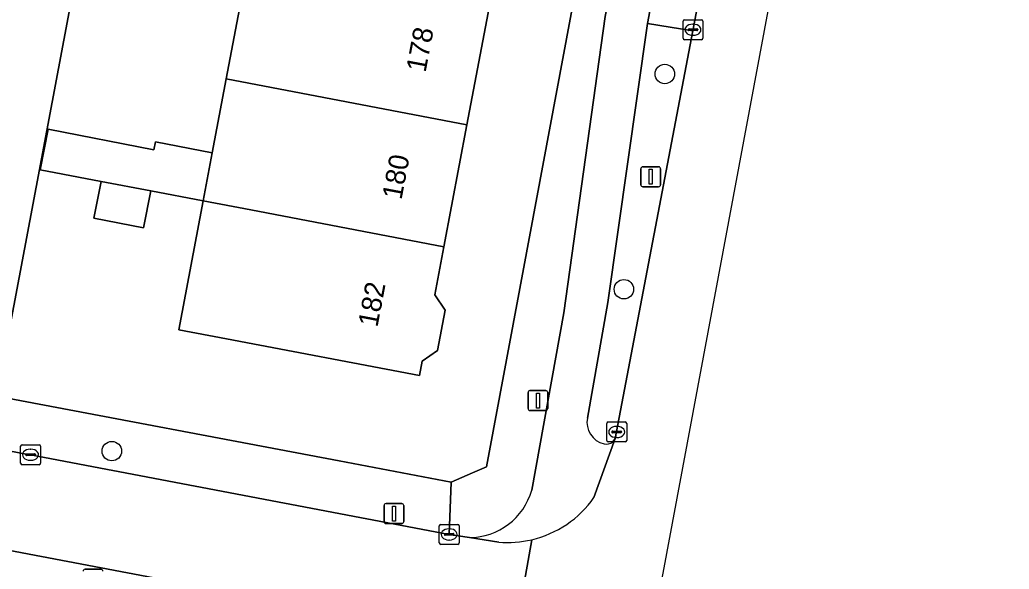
# Model space of a CAD drawing. Extents: x 161258 to 161838, y 380833 to 381727.
# Drawn here: x 161786.15 to 161835.77, y 381531.46 to 381559.03 of the extents above; entities that cross this region are included whole.
import ezdxf

# ---------------------------------------------------------------- set-up
doc = ezdxf.new("R2010")
doc.units = 0
for name, color, linetype in [('IMGEO_Berm_groen', 7, 'Continuous'), ('IMGEO_Boom', 7, 'Continuous'), ('IMGEO_Erf', 7, 'Continuous'), ('IMGEO_Fietspad_open', 7, 'Continuous'), ('IMGEO_Kolk', 7, 'Continuous'), ('IMGEO_Lichtmast', 7, 'Continuous'), ('IMGEO_Pand', 7, 'Continuous'), ('IMGEO_Pand_nummerreeks', 7, 'Continuous'), ('IMGEO_Rijbaan_lokaal_open', 7, 'Continuous'), ('IMGEO_Rijbaan_regionaal_gesloten', 7, 'Continuous'), ('IMGEO_Voetpad_open', 7, 'Continuous')]:
    doc.layers.add(name, color=color, linetype=linetype)

msp = doc.modelspace()

# ---------------------------------------------------------------- linework, layer by layer
at = {"layer": 'IMGEO_Berm_groen'}
for points in [[(161819.903, 381558.473), (161817.626, 381558.84), (161815.643, 381544.847), (161814.615, 381539.044)], [(161815.886, 381537.855), (161816.006, 381538.014), (161819.903, 381558.473)]]:
    msp.add_lwpolyline(points, dxfattribs=at)
for centre, radius, start, end in [((161815.714, 381538.835), 1.119, 169.2571, 256.3919), ((161815.564, 381538.227), 0.492, 256.7259, 310.9123)]:
    msp.add_arc(centre, radius, start, end, dxfattribs=at)
at = {"layer": 'IMGEO_Boom'}
for centre in [(161818.499, 381556.312), (161816.448, 381545.51), (161790.767, 381537.386)]:
    msp.add_circle(centre, 0.489, dxfattribs=at)
at = {"layer": 'IMGEO_Erf'}
for points in [[(161782.505, 381585.389), (161793.109, 381583.267), (161784.977, 381540.142), (161802.164, 381536.901), (161807.78, 381535.827), (161808.863, 381536.294), (161809.558, 381536.593), (161821.924, 381602.839), (161823.603, 381614.49)], [(161809.769, 381560.098), (161808.573, 381553.757), (161807.419, 381547.642), (161806.962, 381545.222), (161807.485, 381544.454), (161807.101, 381542.427), (161806.337, 381541.907), (161806.199, 381541.178), (161796.514, 381543.015), (161794.121, 381543.469), (161795.349, 381549.947), (161792.722, 381550.449), (161792.358, 381548.589), (161789.872, 381549.075), (161790.234, 381550.924), (161787.181, 381551.507), (161787.581, 381553.546), (161792.877, 381552.511), (161792.954, 381552.9), (161795.806, 381552.356), (161796.509, 381556.062), (161797.712, 381562.402)]]:
    msp.add_lwpolyline(points, dxfattribs=at)
at = {"layer": 'IMGEO_Fietspad_open'}
for points in [[(161823.462, 381598.367), (161821.175, 381588.661), (161815.514, 381559.201), (161813.439, 381544.332), (161811.823, 381535.427)], [(161814.615, 381539.044), (161815.643, 381544.847), (161817.626, 381558.84), (161820.504, 381574.1), (161820.891, 381576.15), (161822.952, 381586.933)], [(161814.947, 381535.053), (161816.006, 381538.014), (161815.886, 381537.855)], [(161808.698, 381533.046), (161810.171, 381532.818)]]:
    msp.add_lwpolyline(points, dxfattribs=at)
for centre, radius, start, end in [((161815.714, 381538.835), 1.119, 169.2571, 256.3919), ((161815.564, 381538.227), 0.492, 256.7259, 310.9123), ((161808.685, 381536.305), 3.259, 270.2359, 344.3731), ((161810.611, 381538.095), 5.297, 283.2263, 324.9458), ((161810.612, 381538.134), 5.334, 265.2563, 283.1219)]:
    msp.add_arc(centre, radius, start, end, dxfattribs=at)
at = {"layer": 'IMGEO_Kolk'}
for p, q in [((161819.488, 381559.032), (161820.34, 381559.032)), ((161819.413, 381558.106), (161819.413, 381558.958)), ((161819.672, 381558.526), (161819.672, 381558.538)), ((161819.715, 381558.575), (161820.113, 381558.575)), ((161819.901, 381558.812), (161819.926, 381558.812)), ((161820.156, 381558.538), (161820.156, 381558.526)), ((161820.414, 381558.958), (161820.414, 381558.106)), ((161820.34, 381558.032), (161819.488, 381558.032)), ((161820.11, 381558.489), (161819.712, 381558.489)), ((161819.924, 381558.252), (161819.899, 381558.252)), ((161815.587, 381537.921), (161815.587, 381538.773)), ((161815.662, 381538.847), (161816.514, 381538.847)), ((161816.588, 381538.773), (161816.588, 381537.921)), ((161815.846, 381538.341), (161815.846, 381538.353)), ((161816.284, 381538.304), (161815.886, 381538.304)), ((161815.889, 381538.39), (161816.287, 381538.39)), ((161816.075, 381538.627), (161816.1, 381538.627)), ((161816.33, 381538.353), (161816.33, 381538.341)), ((161786.267, 381537.703), (161787.119, 381537.703)), ((161816.514, 381537.847), (161815.662, 381537.847)), ((161816.098, 381538.067), (161816.073, 381538.067)), ((161786.192, 381536.777), (161786.192, 381537.629)), ((161786.451, 381537.197), (161786.451, 381537.209)), ((161786.494, 381537.246), (161786.892, 381537.246)), ((161786.68, 381537.483), (161786.705, 381537.483)), ((161786.935, 381537.209), (161786.935, 381537.197)), ((161787.193, 381537.629), (161787.193, 381536.777)), ((161787.119, 381536.703), (161786.267, 381536.703)), ((161786.889, 381537.16), (161786.491, 381537.16)), ((161786.703, 381536.923), (161786.678, 381536.923)), ((161807.187, 381532.777), (161807.187, 381533.629)), ((161807.262, 381533.703), (161808.114, 381533.703)), ((161807.489, 381533.246), (161807.887, 381533.246)), ((161807.675, 381533.483), (161807.7, 381533.483)), ((161808.188, 381533.629), (161808.188, 381532.777)), ((161807.446, 381533.197), (161807.446, 381533.209)), ((161807.884, 381533.16), (161807.486, 381533.16)), ((161807.698, 381532.923), (161807.673, 381532.923)), ((161807.93, 381533.209), (161807.93, 381533.197)), ((161808.114, 381532.703), (161807.262, 381532.703))]:
    msp.add_line(p, q, dxfattribs=at)
for points in [[(161819.488, 381559.032), (161820.34, 381559.032)], [(161819.413, 381558.106), (161819.413, 381558.958)], [(161820.414, 381558.958), (161820.414, 381558.106)], [(161820.34, 381558.032), (161819.488, 381558.032)], [(161815.587, 381537.921), (161815.587, 381538.773)], [(161815.662, 381538.847), (161816.514, 381538.847)], [(161816.588, 381538.773), (161816.588, 381537.921)], [(161786.267, 381537.703), (161787.119, 381537.703)], [(161816.514, 381537.847), (161815.662, 381537.847)], [(161786.192, 381536.777), (161786.192, 381537.629)], [(161787.193, 381537.629), (161787.193, 381536.777)], [(161787.119, 381536.703), (161786.267, 381536.703)], [(161807.187, 381532.777), (161807.187, 381533.629)], [(161807.262, 381533.703), (161808.114, 381533.703)], [(161808.188, 381533.629), (161808.188, 381532.777)], [(161808.114, 381532.703), (161807.262, 381532.703)]]:
    msp.add_lwpolyline(points, dxfattribs=at)
for centre, radius, start, end in [((161819.49, 381558.956), 0.0765, 91.552, 178.448), ((161819.49, 381558.956), 0.0765, 91.552, 178.448), ((161820.338, 381558.956), 0.0765, 1.552, 88.448), ((161820.338, 381558.956), 0.0765, 1.552, 88.448), ((161819.712, 381558.535), 0.0403, 85.8775, 175.7526), ((161819.709, 381558.525), 0.0366, 178.938, 274.7102), ((161820.113, 381558.532), 0.043, 264.8664, 352.4533), ((161820.117, 381558.537), 0.0386, 1.7309, 96.639), ((161819.49, 381558.108), 0.0765, 181.552, 268.448), ((161819.49, 381558.108), 0.0765, 181.552, 268.448), ((161820.338, 381558.108), 0.0765, 271.552, 358.448), ((161820.338, 381558.108), 0.0765, 271.552, 358.448), ((161815.664, 381538.771), 0.0765, 91.552, 178.448), ((161815.664, 381538.771), 0.0765, 91.552, 178.448), ((161816.512, 381538.771), 0.0765, 1.552, 88.448), ((161816.512, 381538.771), 0.0765, 1.552, 88.448), ((161815.886, 381538.35), 0.0403, 85.8775, 175.7526), ((161815.883, 381538.34), 0.0366, 178.938, 274.7102), ((161816.287, 381538.347), 0.043, 264.8664, 352.4533), ((161816.291, 381538.352), 0.0386, 1.7309, 96.639), ((161786.269, 381537.627), 0.0765, 91.552, 178.448), ((161786.269, 381537.627), 0.0765, 91.552, 178.448), ((161787.117, 381537.627), 0.0765, 1.552, 88.448), ((161787.117, 381537.627), 0.0765, 1.552, 88.448), ((161815.664, 381537.923), 0.0765, 181.552, 268.448), ((161815.664, 381537.923), 0.0765, 181.552, 268.448), ((161816.512, 381537.923), 0.0765, 271.552, 358.448), ((161816.512, 381537.923), 0.0765, 271.552, 358.448), ((161786.491, 381537.206), 0.0403, 85.8775, 175.7526), ((161786.488, 381537.196), 0.0366, 178.938, 274.7102), ((161786.892, 381537.203), 0.043, 264.8664, 352.4533), ((161786.896, 381537.208), 0.0386, 1.7309, 96.639), ((161786.269, 381536.779), 0.0765, 181.552, 268.448), ((161786.269, 381536.779), 0.0765, 181.552, 268.448), ((161787.117, 381536.779), 0.0765, 271.552, 358.448), ((161787.117, 381536.779), 0.0765, 271.552, 358.448), ((161807.264, 381533.627), 0.0765, 91.552, 178.448), ((161807.264, 381533.627), 0.0765, 91.552, 178.448), ((161807.486, 381533.206), 0.0403, 85.8775, 175.7526), ((161807.891, 381533.208), 0.0386, 1.7309, 96.639), ((161808.112, 381533.627), 0.0765, 1.552, 88.448), ((161808.112, 381533.627), 0.0765, 1.552, 88.448), ((161807.264, 381532.779), 0.0765, 181.552, 268.448), ((161807.264, 381532.779), 0.0765, 181.552, 268.448), ((161807.483, 381533.196), 0.0366, 178.938, 274.7102), ((161807.887, 381533.203), 0.043, 264.8664, 352.4533), ((161808.112, 381532.779), 0.0765, 271.552, 358.448), ((161808.112, 381532.779), 0.0765, 271.552, 358.448)]:
    msp.add_arc(centre, radius, start, end, dxfattribs=at)
for centre, major_axis, ratio, start_param, end_param in [((161819.9, 381558.532), (-0.387, 0.002), 0.722429, 4.712389, 7.853982), ((161819.925, 381558.532), (-0.39, 0.002), 0.717154, 1.570796, 4.712389), ((161816.074, 381538.347), (-0.387, 0.002), 0.722429, 4.712389, 7.853982), ((161816.099, 381538.347), (-0.39, 0.002), 0.717154, 1.570796, 4.712389), ((161786.679, 381537.203), (-0.387, 0.002), 0.722429, 4.712389, 7.853982), ((161786.704, 381537.203), (-0.39, 0.002), 0.717154, 1.570796, 4.712389), ((161807.674, 381533.203), (-0.387, 0.002), 0.722429, 4.712389, 7.853982), ((161807.699, 381533.203), (-0.39, 0.002), 0.717154, 1.570796, 4.712389)]:
    msp.add_ellipse(centre, major_axis=major_axis, ratio=ratio, start_param=start_param, end_param=end_param, dxfattribs=at)
at = {"layer": 'IMGEO_Lichtmast'}
for p, q in [((161817.398, 381551.654), (161818.188, 381551.654)), ((161818.188, 381551.654), (161817.398, 381551.654)), ((161817.298, 381550.754), (161817.298, 381551.554)), ((161817.298, 381551.554), (161817.298, 381550.754)), ((161818.288, 381551.554), (161818.288, 381550.754)), ((161818.288, 381550.754), (161818.288, 381551.554)), ((161818.188, 381550.654), (161817.398, 381550.654)), ((161817.398, 381550.654), (161818.188, 381550.654)), ((161811.639, 381539.523), (161811.639, 381540.323)), ((161811.639, 381540.323), (161811.639, 381539.523)), ((161811.739, 381540.423), (161812.529, 381540.423)), ((161812.529, 381540.423), (161811.739, 381540.423)), ((161812.629, 381540.323), (161812.629, 381539.523)), ((161812.629, 381539.523), (161812.629, 381540.323)), ((161812.529, 381539.423), (161811.739, 381539.423)), ((161811.739, 381539.423), (161812.529, 381539.423)), ((161804.519, 381534.75), (161805.309, 381534.75)), ((161805.309, 381534.75), (161804.519, 381534.75)), ((161804.419, 381533.85), (161804.419, 381534.65)), ((161804.419, 381534.65), (161804.419, 381533.85)), ((161805.409, 381534.65), (161805.409, 381533.85)), ((161805.409, 381533.85), (161805.409, 381534.65)), ((161805.309, 381533.75), (161804.519, 381533.75)), ((161804.519, 381533.75), (161805.309, 381533.75)), ((161789.427, 381531.459), (161790.217, 381531.459)), ((161790.217, 381531.459), (161789.427, 381531.459))]:
    msp.add_line(p, q, dxfattribs=at)
for points in [[(161817.718, 381551.529), (161817.868, 381551.529), (161817.868, 381550.779), (161817.718, 381550.779), (161817.718, 381551.529)], [(161812.059, 381540.298), (161812.209, 381540.298), (161812.209, 381539.548), (161812.059, 381539.548), (161812.059, 381540.298)], [(161804.839, 381534.625), (161804.989, 381534.625), (161804.989, 381533.875), (161804.839, 381533.875), (161804.839, 381534.625)]]:
    msp.add_lwpolyline(points, dxfattribs=at)
for centre, start, end in [((161817.398, 381551.554), 90, 180), ((161817.398, 381551.554), 90, 180), ((161818.188, 381551.554), 0, 90), ((161818.188, 381551.554), 360, 90), ((161817.398, 381550.754), 180, 270), ((161817.398, 381550.754), 180, 270), ((161818.188, 381550.754), 270, 0), ((161818.188, 381550.754), 270, 0), ((161811.739, 381540.323), 90, 180), ((161811.739, 381540.323), 90, 180), ((161812.529, 381540.323), 0, 90), ((161812.529, 381540.323), 360, 90), ((161811.739, 381539.523), 180, 270), ((161811.739, 381539.523), 180, 270), ((161812.529, 381539.523), 270, 0), ((161812.529, 381539.523), 270, 0), ((161804.519, 381534.65), 90, 180), ((161804.519, 381534.65), 90, 180), ((161805.309, 381534.65), 0, 90), ((161805.309, 381534.65), 360, 90), ((161804.519, 381533.85), 180, 270), ((161804.519, 381533.85), 180, 270), ((161805.309, 381533.85), 270, 0), ((161805.309, 381533.85), 270, 0), ((161789.427, 381531.359), 90, 180), ((161789.427, 381531.359), 90, 180), ((161790.217, 381531.359), 0, 90), ((161790.217, 381531.359), 360, 90)]:
    msp.add_arc(centre, 0.1, start, end, dxfattribs=at)
at = {"layer": 'IMGEO_Pand'}
for points in [[(161797.712, 381562.402), (161796.509, 381556.062), (161808.573, 381553.757), (161809.769, 381560.098), (161800.105, 381561.945)], [(161808.573, 381553.757), (161796.509, 381556.062), (161795.806, 381552.356), (161795.349, 381549.947), (161797.743, 381549.49), (161807.419, 381547.642)], [(161795.806, 381552.356), (161792.954, 381552.9), (161792.877, 381552.511), (161787.581, 381553.546), (161787.181, 381551.507), (161790.234, 381550.924), (161792.722, 381550.449), (161795.349, 381549.947)], [(161792.722, 381550.449), (161790.234, 381550.924), (161789.872, 381549.075), (161792.358, 381548.589)], [(161807.419, 381547.642), (161797.743, 381549.49), (161795.349, 381549.947), (161794.121, 381543.469), (161796.514, 381543.015), (161806.199, 381541.178), (161806.337, 381541.907), (161807.101, 381542.427), (161807.485, 381544.454), (161806.962, 381545.222)]]:
    msp.add_lwpolyline(points, close=True, dxfattribs=at)
at = {"layer": 'IMGEO_Rijbaan_lokaal_open'}
msp.add_lwpolyline([(161793.109, 381583.267), (161782.505, 381585.389), (161781.962, 381582.492), (161781.435, 381579.687), (161780.909, 381576.885), (161780.383, 381574.083), (161779.83, 381571.134), (161781.308, 381570.848), (161781.392, 381571.272), (161786.642, 381570.271), (161787.039, 381567.813), (161786.221, 381563.671), (161786.11, 381563.693), (161785.277, 381558.94), (161783.734, 381550.581), (161782.826, 381545.664), (161781.913, 381540.72), (161784.977, 381540.142)], close=True, dxfattribs=at)
for points in [[(161786.693, 381537.202), (161786.472, 381537.226), (161780.553, 381538.362), (161779.615, 381533.541), (161785.57, 381532.417), (161806.867, 381528.363), (161807.12, 381528.313), (161810.875, 381527.563), (161811.823, 381532.939)], [(161810.171, 381532.818), (161808.698, 381533.046), (161807.687, 381533.202), (161786.693, 381537.202)]]:
    msp.add_lwpolyline(points, dxfattribs=at)
msp.add_arc((161810.612, 381538.134), 5.334, 265.2563, 283.1219, dxfattribs=at)
at = {"layer": 'IMGEO_Rijbaan_regionaal_gesloten'}
for points in [[(161732.705, 381071.484), (161732.705, 381071.238), (161742.349, 381122.541), (161776.386, 381306.634), (161779.513, 381323.547), (161779.709, 381323.516), (161781.032, 381330.976), (161790.829, 381386.201), (161813.475, 381504.752), (161831.216, 381599.902), (161831.886, 381604.233), (161835.772, 381629.362), (161830.258, 381630.974)], [(161829.955, 381614.672), (161829.558, 381611.574), (161828.749, 381606.032), (161828.709, 381605.76), (161828.312, 381603.298), (161827.482, 381598.619), (161825.18, 381586.469), (161823.132, 381575.72), (161822.744, 381573.65), (161819.903, 381558.473), (161816.006, 381538.014), (161814.947, 381535.053)], [(161811.823, 381532.939), (161810.875, 381527.563), (161812.916, 381527.15), (161813.737, 381526.947)]]:
    msp.add_lwpolyline(points, dxfattribs=at)
msp.add_arc((161810.611, 381538.095), 5.297, 283.2263, 324.9458, dxfattribs=at)
at = {"layer": 'IMGEO_Voetpad_open'}
for points in [[(161825.925, 381631.335), (161823.38, 381630.949), (161824.572, 381627.383), (161824.336, 381623.682), (161823.603, 381614.49), (161821.924, 381602.839), (161809.558, 381536.593), (161808.863, 381536.294), (161807.78, 381535.827), (161807.687, 381533.202), (161808.698, 381533.046)], [(161813.439, 381544.332), (161815.514, 381559.201), (161821.175, 381588.661), (161823.462, 381598.367)], [(161811.823, 381535.427), (161813.439, 381544.332)]]:
    msp.add_lwpolyline(points, dxfattribs=at)
for points in [[(161820.504, 381574.1), (161817.626, 381558.84), (161819.903, 381558.473), (161822.744, 381573.65)], [(161781.913, 381540.72), (161742.891, 381548.079), (161742.875, 381545.494), (161743.113, 381545.444), (161764.536, 381541.372), (161764.753, 381541.307), (161769.655, 381540.387), (161774.599, 381539.471), (161775.772, 381539.26), (161780.309, 381538.416), (161780.553, 381538.362), (161786.472, 381537.226), (161786.693, 381537.202), (161807.687, 381533.202), (161807.78, 381535.827), (161802.164, 381536.901), (161784.977, 381540.142)], [(161779.615, 381533.541), (161774.842, 381534.445), (161768.171, 381535.745), (161763.484, 381536.649), (161762.151, 381536.852), (161742.121, 381540.664), (161741.669, 381540.75), (161741.711, 381538.033), (161779.178, 381531.082), (161780.173, 381530.897), (161792.473, 381528.615), (161806.742, 381525.9), (161807.325, 381525.789), (161807.12, 381528.313), (161806.867, 381528.363), (161785.57, 381532.417)]]:
    msp.add_lwpolyline(points, close=True, dxfattribs=at)
msp.add_arc((161808.685, 381536.305), 3.259, 270.2359, 344.3731, dxfattribs=at)

# ---------------------------------------------------------------- texts
at = {"layer": 'IMGEO_Pand_nummerreeks'}
for s, rotation, p in [('178', 79.3128, (161806.5, 381556.358)), ('180', 79.3145, (161805.294, 381549.968)), ('182', 79.3128, (161804.087, 381543.574))]:
    msp.add_text(s, height=1, rotation=rotation, dxfattribs=at).set_placement(p)

doc.saveas('drawing.dxf')
